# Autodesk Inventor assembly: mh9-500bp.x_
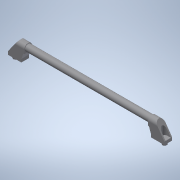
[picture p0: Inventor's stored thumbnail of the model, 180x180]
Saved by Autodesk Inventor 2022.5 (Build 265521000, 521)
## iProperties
Part Number: mh9-500bp.x_
Material: 一般
Document SubType Name: Assembly
Designer: ImaoCorp
Sending System: SOLIDWORKS 2017-2017317
MC: AMD64
MC_MODEL: Intel64 Family 6 Model 60 Stepping 3, GenuineIntel
OS: Windows_NT
FRU: Parasolid Version 29.0, build 201,  4-17-2017
FORMAT: text
GUISE: transmit
KEY: mh9-500bp
FILE: mh9-500bp.x_t
DATE: Fri Jul 26 11:47:44 2019
Author: ImaoCorp
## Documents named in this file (4)
- X:\14_SW2022-Inv2022\00_全2023-1023新製品(TCC)まで\m\mh9-500bp\MH9-500BP.iam
- X:\14_SW2022-Inv2022\00_全2023-1023新製品(TCC)まで\m\mh9-500bp\mh9-500bp_01.ipt
- X:\14_SW2022-Inv2022\00_全2023-1023新製品(TCC)まで\m\mh9-500bp\mh9-500bp_02.ipt
- X:\14_SW2022-Inv2022\00_全2023-1023新製品(TCC)まで\m\mh9-500bp\mh9-500bp_03.ipt
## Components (3 placed, 3 different names)
1. mh9-500bp_01
2. mh9-500bp_02
3. mh9-500bp_03
